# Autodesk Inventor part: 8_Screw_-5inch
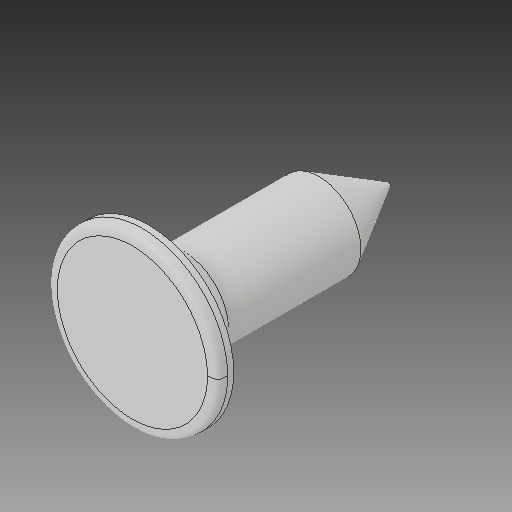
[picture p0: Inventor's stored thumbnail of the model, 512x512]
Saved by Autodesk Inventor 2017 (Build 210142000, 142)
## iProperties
Created: 2017-05
Part Number: 8_Screw_-5inch
Material: Generic
Document SubType Name: Modeling
Designer: Savy
Density: 1 g/cm^3
Appearance: Default
Author: Savy
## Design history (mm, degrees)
feature "SOLID1"
body "Solid1"
